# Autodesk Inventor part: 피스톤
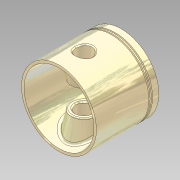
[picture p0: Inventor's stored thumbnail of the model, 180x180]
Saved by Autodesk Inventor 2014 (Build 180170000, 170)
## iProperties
Manager: KYOUNG IL JANG
Company: 한국ATC센터
Created: 2012-10
Part Number: 피스톤
Document SubType Name: Modeling
Density: 1 g/cm^3
Checked By: KYOUNG IL JANG
Vendor: CBT Solutions
Designer: KYOUNG IL JANG
Material: Generic
Appearance: _시험_금속-티타늄(광택)
Author: KYOUNG IL JANG
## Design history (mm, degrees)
revolve "회전1" stored, may be unused: angle "d8" = 90 deg
node "작업 평면1"
sketch "스케치2"
  geometry: L1 (-28, 0)-(28, 0) reference; C1 r 10 at (0, 20); C2 r 6.5 at (0, 20); 1 further point
  constraints: 2 centre point, 1 coincident, 1 vertical alignment
  dimensions: "d10" = 20 diameter of C1; "d13" = 20 distance from line of C1.centre L1; "d14" = 13 diameter of C2
extrude "돌출1" join sketch "스케치2" stored distance "d11" = 10; taper "d12" = 12 deg
extrude "돌출2" cut sketch "스케치2" stored distance "d15" = 10; taper "d16" = 0 deg
fillet "모깎기1" dims "d17" = 2, "d21" = 3
chamfer "모따기1" distance "d18" = 1; stored, may be unused: second distance "d19" = 2, angle "d20" = 45 deg
chamfer "모따기2" distance "d22" = 1; stored, may be unused: second distance "d23" = 2, angle "d24" = 45 deg
fillet "모깎기2" dims "d25" = 1
node "솔리드1"
mirror "대칭1"
sketch "스케치1"
  geometry: L1 (0, 0)-(0, 50); L2 (0, 50)-(30, 50); L3 (30, 50)-(30, 45); L4 (30, 45)-(28, 45); L5 (28, 45)-(28, 44); L6 (28, 44)-(30, 44); L7 (30, 44)-(30, 43); L8 (30, 43)-(28, 43); L9 (28, 43)-(28, 42); L10 (28, 42)-(30, 42); L11 (30, 42)-(30, 0); L12 (30, 0)-(28, 0); L13 (28, 0)-(23, 45); L14 (23, 45)-(0, 45)
  constraints: 28 end point, 10 parallel, 5 collinear, 2 perpendicular, 2 point on line, 1 vertical
  dimensions: "d0" = 50 distance of L1.start L1.end; "d1" = 60 diameter of L3 L1; "d2" = 5 distance between parallel lines of L2 L14; "d3" = 2 distance of L11.end L12.end; "d5" = 5 distance of L2.end L3.end; "d6" = 1 distance of L4.end L5.end; "d7" = 2 distance of L9.end L10.end; "d26" = 46 diameter of L13.end L1
